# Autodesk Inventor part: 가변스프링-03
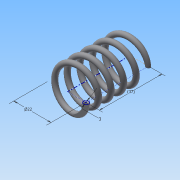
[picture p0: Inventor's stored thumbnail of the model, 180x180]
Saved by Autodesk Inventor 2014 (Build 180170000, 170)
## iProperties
Created: 2015-09
Part Number: 가변스프링-03
Material: 강철, 탄소
Document SubType Name: Modeling
Designer: study
Density: 7.87 g/cm^3
Appearance: 반연마
Mass: 18.9154 g
Surface Area: 32.5802 cm^2
Volume: 2.40348 cm^3
Author: study
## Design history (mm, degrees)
sketch "스케치1"
  geometry: L1 (0, 0)-(11, 0); L2 (11, 0)-(11, 40.095); L3 (11, 40.095)-(0, 40.095); L4 (0, 40.095)-(0, 0); C1 r 1.5 at (11, 0)
  constraints: 8 end point, 2 parallel, 1 centre point, 1 coincident, 1 horizontal, 1 perpendicular
  dimensions: "d0" = 22 diameter of L2 L4; "d1" = 3 diameter of C1; "d2" = 40.0955 distance of L1.end L2.end (derived)
feature "코일1" sketch "스케치1" pitch "d3" = 10; turns "d5" = 5; dims "d4" = 40.0955 (= d2), "d6" = 0, angle "d7" = 90 deg, angle "d8" = 90 deg, "d9" = 0, "d10" = 0
sketch "스케치2"
  geometry: L1 (-12.5, 0)-(-9.5, 0) reference; 1 further point
  constraints: 1 horizontal alignment
extrude "돌출1" cut sketch "스케치2" stored distance "d11" = 10; taper "d12" = 0 deg
node "작업 평면1"
sketch "스케치3"
  geometry: L1 (-9.5, 0)-(-12.5, 0) reference; 1 further point
  constraints: 1 horizontal alignment
extrude "돌출2" cut sketch "스케치3" stored distance "d14" = 10; taper "d15" = 0 deg
node "솔리드1"
node "절단 모서리 투영1"
node "절단 모서리 투영2"
other parameters: "d13" = 40.0955 (= d2)
